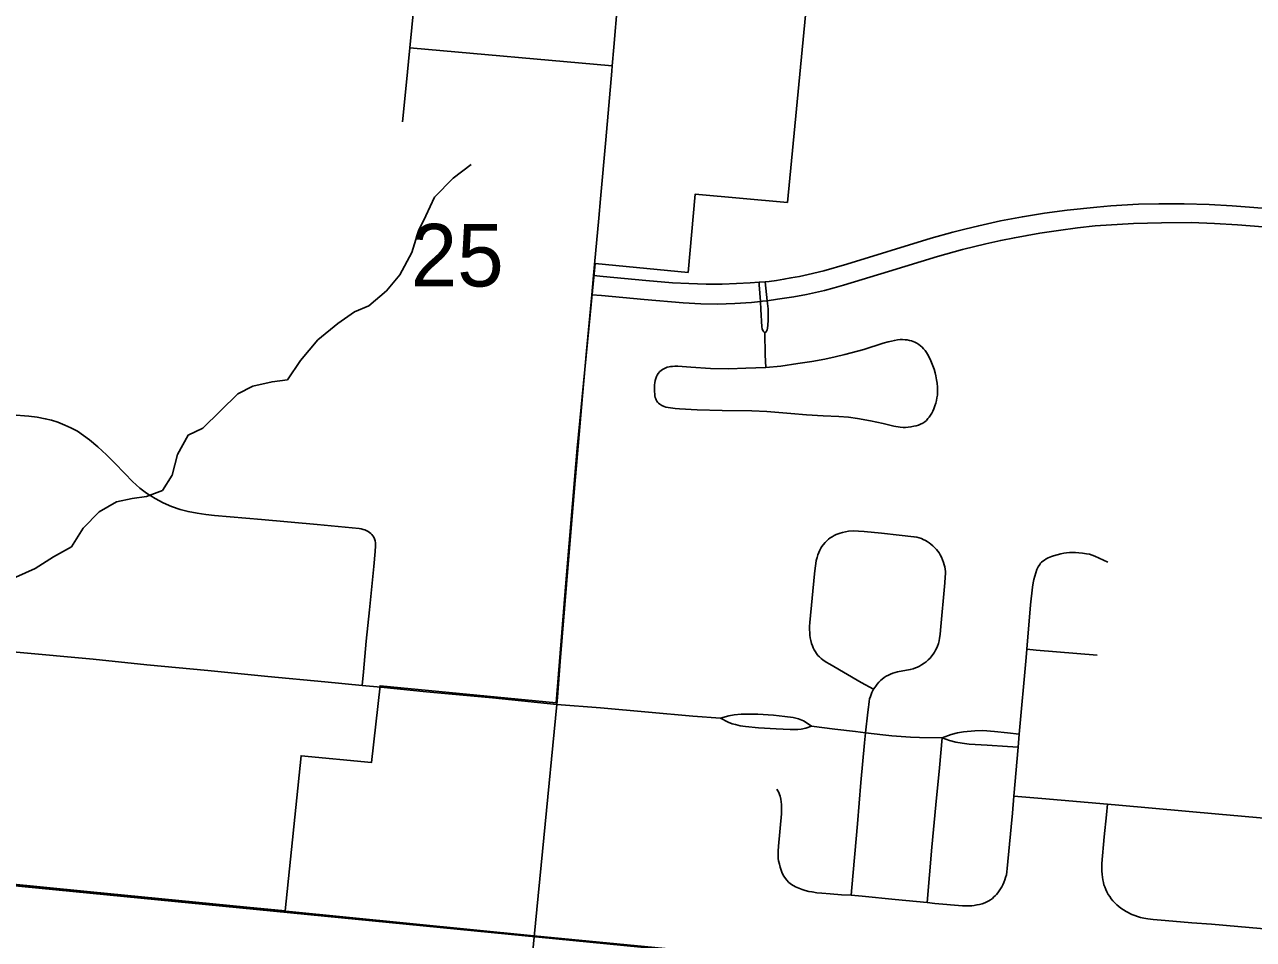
# Model space of a CAD drawing. Extents: x -38.1 to 35.9, y -2.7 to 28.5.
# Drawn here: x 11.157 to 11.979, y 15.188 to 15.8 of the extents above; entities that cross this region are included whole.
import ezdxf

# ---------------------------------------------------------------- set-up
doc = ezdxf.new("R2010")
doc.units = 0
for name, color, linetype in [('GM_X_City_Street', 7, 'Continuous'), ('GM_X_City_Street_Text', 7, 'Continuous'), ('GM_X_Interchange_Ramps', 7, 'Continuous'), ('GM_X_Major_River_Text', 7, 'Continuous'), ('GM_X_Minor_River', 7, 'Continuous'), ('GM_X_Section', 7, 'Continuous'), ('GM_X_US_Route', 7, 'Continuous')]:
    doc.layers.add(name, color=color, linetype=linetype)

msp = doc.modelspace()

# ---------------------------------------------------------------- linework, layer by layer
at = {"layer": 'GM_X_City_Street'}
for points in [[(11.65249, 15.59353), (11.65169, 15.59415), (11.65106, 15.59493), (11.65056, 15.59605), (11.65039, 15.59747), (11.64984, 15.60906), (11.64948, 15.61444), (11.64874, 15.62564), (11.64863, 15.62731)], [(11.65249, 15.59353), (11.65312, 15.59402), (11.65361, 15.59464), (11.65394, 15.59538), (11.65423, 15.59653), (11.65444, 15.59863), (11.65466, 15.60188), (11.65458, 15.60953), (11.65399, 15.61489), (11.65271, 15.62758)], [(11.65318, 15.57039), (11.63966, 15.56974), (11.62844, 15.56947), (11.61599, 15.56972), (11.60294, 15.57051), (11.5943, 15.57112), (11.59234, 15.57113), (11.59066, 15.57105), (11.58938, 15.57093), (11.58835, 15.57072), (11.5872, 15.57043), (11.58611, 15.57003), (11.58498, 15.56944), (11.58406, 15.56896), (11.58313, 15.56829), (11.58229, 15.56753), (11.58119, 15.56626), (11.5805, 15.56517), (11.58002, 15.56427), (11.57951, 15.56295), (11.57915, 15.56151), (11.5789, 15.56012), (11.57871, 15.5586), (11.57858, 15.55559), (11.57865, 15.55403), (11.57876, 15.55258), (11.57894, 15.55128), (11.57917, 15.55025), (11.57943, 15.5493), (11.57974, 15.54861), (11.58013, 15.54782), (11.58059, 15.54718), (11.58132, 15.54643), (11.58215, 15.54571), (11.58356, 15.54489), (11.58517, 15.54422), (11.58629, 15.54384), (11.58777, 15.54355), (11.58927, 15.54331), (11.59238, 15.54289), (11.5954, 15.54262), (11.60714, 15.54197), (11.62388, 15.54162), (11.64377, 15.54128), (11.65372, 15.54083), (11.66983, 15.53949), (11.68033, 15.53863), (11.69147, 15.53804), (11.70204, 15.53758), (11.70839, 15.53698), (11.71445, 15.53615), (11.72305, 15.53459), (11.72733, 15.53366), (11.73157, 15.53272), (11.73879, 15.53103), (11.743, 15.53041), (11.7449, 15.53023), (11.74661, 15.53026), (11.74827, 15.53036), (11.75021, 15.53056), (11.75206, 15.53094), (11.75371, 15.53133), (11.75514, 15.53176), (11.75652, 15.53233), (11.75806, 15.53307), (11.75953, 15.53401), (11.76053, 15.53488), (11.76153, 15.5361), (11.76241, 15.53714), (11.76329, 15.53849), (11.7641, 15.53977), (11.76479, 15.54113), (11.7655, 15.54269), (11.76622, 15.54456), (11.76673, 15.54635), (11.76723, 15.54817), (11.76759, 15.54996), (11.76783, 15.55173), (11.76792, 15.55449), (11.76783, 15.55719), (11.76763, 15.55974), (11.76734, 15.56204), (11.76685, 15.56463), (11.76632, 15.5668), (11.76566, 15.56911), (11.76486, 15.57145), (11.76397, 15.57364), (11.76297, 15.57595), (11.76128, 15.57917), (11.76049, 15.5804), (11.75961, 15.58166), (11.75865, 15.58278), (11.75765, 15.58387), (11.75655, 15.58484), (11.75536, 15.58573), (11.75408, 15.58652), (11.7528, 15.5872), (11.7517, 15.58768), (11.75061, 15.58805), (11.74919, 15.58846), (11.74765, 15.58874), (11.74628, 15.58887), (11.74455, 15.58895), (11.74307, 15.58891), (11.74116, 15.58875), (11.73913, 15.58842), (11.73727, 15.588), (11.73485, 15.58739), (11.7317, 15.58646), (11.71861, 15.58244), (11.706, 15.57902), (11.6994, 15.57732), (11.69265, 15.57587), (11.68386, 15.57436), (11.67457, 15.57288), (11.66305, 15.57129), (11.65318, 15.57039), (11.65277, 15.57886), (11.65249, 15.59353)], [(11.7198, 15.32596), (11.72129, 15.33965), (11.72168, 15.34316), (11.72193, 15.34495), (11.72221, 15.34693), (11.72255, 15.34861), (11.72302, 15.35013), (11.72354, 15.35165), (11.72403, 15.35293), (11.72464, 15.35416), (11.72518, 15.35514), (11.72591, 15.35621), (11.72662, 15.35716), (11.72764, 15.35847), (11.72871, 15.35971), (11.72985, 15.36082), (11.73093, 15.36176), (11.73235, 15.36286), (11.7336, 15.36373), (11.73512, 15.36454), (11.73652, 15.36521), (11.73807, 15.36583), (11.73952, 15.36628), (11.74117, 15.36671), (11.74972, 15.36824), (11.75157, 15.36875), (11.75315, 15.36931), (11.75452, 15.36986), (11.75587, 15.37055), (11.75732, 15.37134), (11.75893, 15.37244), (11.76032, 15.37343), (11.76172, 15.37471), (11.76299, 15.37594), (11.76417, 15.37733), (11.76509, 15.37853), (11.76591, 15.37977), (11.76669, 15.38112), (11.76734, 15.38239), (11.76803, 15.38383), (11.76857, 15.38574), (11.76899, 15.38741), (11.76934, 15.38926), (11.76965, 15.39164), (11.76998, 15.3946), (11.77288, 15.42627), (11.77315, 15.43007), (11.77323, 15.43239), (11.77318, 15.43381), (11.77301, 15.43537), (11.77277, 15.43685), (11.77242, 15.43828), (11.77191, 15.43994), (11.77126, 15.4417), (11.77051, 15.44338), (11.7697, 15.44496), (11.76895, 15.44622), (11.76811, 15.44749), (11.76719, 15.44865), (11.76619, 15.44975), (11.76492, 15.45099), (11.76353, 15.45218), (11.76238, 15.453), (11.76109, 15.4539), (11.75982, 15.45465), (11.75845, 15.45527), (11.75719, 15.4558), (11.75565, 15.45628), (11.75403, 15.45671), (11.75212, 15.45705), (11.74238, 15.45822), (11.73038, 15.45937), (11.71886, 15.46052), (11.71503, 15.46086), (11.71149, 15.46096), (11.70851, 15.46078), (11.7064, 15.46044), (11.70436, 15.45998), (11.7029, 15.45958), (11.7015, 15.45911), (11.70007, 15.45852), (11.69878, 15.45789), (11.69752, 15.45712), (11.69625, 15.45633), (11.69497, 15.45539), (11.69386, 15.45436), (11.69279, 15.45325), (11.69155, 15.45177), (11.69061, 15.4505), (11.68987, 15.44933), (11.68913, 15.44799), (11.68859, 15.44665), (11.68798, 15.44503), (11.68741, 15.44322), (11.68687, 15.44113), (11.68649, 15.43909), (11.68605, 15.43611), (11.68566, 15.43217), (11.68258, 15.39963), (11.68239, 15.39699), (11.68234, 15.39476), (11.68243, 15.39304), (11.68261, 15.39115), (11.68284, 15.38938), (11.68325, 15.38759), (11.68375, 15.38572), (11.68428, 15.38414), (11.68485, 15.38276), (11.68551, 15.38143), (11.68625, 15.38009), (11.6871, 15.37891), (11.68798, 15.37771), (11.68902, 15.37667), (11.69012, 15.37566), (11.69126, 15.37476), (11.69345, 15.37323), (11.69587, 15.37183), (11.71687, 15.35967), (11.72518, 15.35514)], [(11.66039, 15.2883), (11.66171, 15.286), (11.66229, 15.28472), (11.66272, 15.28357), (11.66319, 15.28164), (11.66344, 15.27978), (11.66362, 15.27806), (11.66368, 15.27658), (11.66362, 15.27422), (11.66349, 15.27177), (11.66156, 15.25016), (11.66128, 15.24679), (11.66125, 15.24381), (11.66142, 15.24193), (11.66169, 15.24021), (11.66216, 15.23805), (11.66263, 15.23606), (11.66327, 15.23412), (11.66382, 15.23265), (11.66452, 15.23121), (11.66514, 15.22999), (11.66685, 15.22758), (11.66846, 15.22587), (11.67031, 15.22445), (11.67291, 15.22299), (11.67516, 15.222), (11.67742, 15.22115), (11.6795, 15.22047), (11.68181, 15.21988), (11.68403, 15.21946), (11.68727, 15.219), (11.6906, 15.21867), (11.69619, 15.21821), (11.70378, 15.21765), (11.71009, 15.21722), (11.71751, 15.21655), (11.73952, 15.21452), (11.76095, 15.21237), (11.76612, 15.21186), (11.78465, 15.21025), (11.78892, 15.21017), (11.79081, 15.21025), (11.79254, 15.21045), (11.79435, 15.21078), (11.79607, 15.21116), (11.79788, 15.21164), (11.79951, 15.21227), (11.80088, 15.21283), (11.80219, 15.21355), (11.80339, 15.21427), (11.80464, 15.21521), (11.80571, 15.21613), (11.80656, 15.21686), (11.80742, 15.21785), (11.80828, 15.21896), (11.80914, 15.22019), (11.81008, 15.22164), (11.81087, 15.2229), (11.81161, 15.2242), (11.81231, 15.22578), (11.81301, 15.22751), (11.8135, 15.22915), (11.81398, 15.23099), (11.81432, 15.23289), (11.81463, 15.23519), (11.81721, 15.26301), (11.81811, 15.27228), (11.81907, 15.28356), (11.82187, 15.31634), (11.82261, 15.32501), (11.82718, 15.37629), (11.82769, 15.38193), (11.83025, 15.41148), (11.83146, 15.42336), (11.83191, 15.42635), (11.83241, 15.42857), (11.83303, 15.43079), (11.83368, 15.43297), (11.83442, 15.43506), (11.83537, 15.43704), (11.83629, 15.43848), (11.83689, 15.43934), (11.83759, 15.44005), (11.83849, 15.44082), (11.83948, 15.44152), (11.84067, 15.44222), (11.84202, 15.44292), (11.84305, 15.44341), (11.84416, 15.44386), (11.84544, 15.44435), (11.8479, 15.44506), (11.8505, 15.44562), (11.85243, 15.446), (11.85427, 15.44628), (11.85625, 15.44645), (11.85809, 15.44654), (11.86032, 15.44649), (11.86253, 15.44638), (11.86492, 15.44613), (11.86755, 15.44575), (11.86956, 15.44534), (11.87137, 15.44481), (11.87322, 15.44411), (11.88197, 15.44004)], [(11.82769, 15.38193), (11.83401, 15.3813), (11.87471, 15.37776)], [(11.5133, 15.34492), (11.5426, 15.34262), (11.57467, 15.33974), (11.60434, 15.33717), (11.6228, 15.33579)], [(11.6228, 15.33579), (11.62831, 15.33736), (11.63201, 15.33802), (11.63661, 15.33835), (11.64097, 15.33851), (11.6477, 15.33834), (11.6583, 15.33774), (11.66571, 15.33695), (11.67138, 15.33612), (11.675, 15.33522), (11.67821, 15.33399), (11.68083, 15.33227), (11.68355, 15.33029)], [(11.6228, 15.33579), (11.62798, 15.333), (11.63053, 15.33202), (11.63277, 15.33138), (11.63603, 15.3307), (11.63955, 15.33023), (11.64825, 15.32928), (11.66011, 15.32856), (11.66933, 15.32807), (11.67442, 15.32815), (11.67673, 15.3284), (11.67985, 15.32914), (11.68355, 15.33029)], [(11.68355, 15.33029), (11.69934, 15.32846), (11.71298, 15.32682), (11.7198, 15.32596), (11.73131, 15.32451), (11.73732, 15.32385), (11.74357, 15.32344), (11.74982, 15.32304), (11.75586, 15.3228), (11.7711, 15.32254)], [(11.71009, 15.21722), (11.71056, 15.22243), (11.71443, 15.265), (11.71662, 15.29279), (11.71916, 15.3193), (11.7198, 15.32596)], [(11.76095, 15.21237), (11.76409, 15.2494), (11.76676, 15.27781), (11.76923, 15.30259), (11.7711, 15.32254)], [(11.7711, 15.32254), (11.77702, 15.32484), (11.78122, 15.32591), (11.7854, 15.32665), (11.79281, 15.32736), (11.79833, 15.32742), (11.80604, 15.3269), (11.81484, 15.32592), (11.82261, 15.32501)], [(11.7711, 15.32254), (11.77603, 15.32081), (11.78015, 15.31974), (11.78442, 15.31901), (11.78919, 15.31843), (11.80127, 15.31769), (11.8147, 15.31682), (11.82187, 15.31634)], [(11.81907, 15.28356), (11.83782, 15.28203), (11.88167, 15.27814), (11.8892, 15.27747), (11.95604, 15.27153), (11.98884, 15.26854), (12.02289, 15.2657)], [(11.88167, 15.27814), (11.88098, 15.27116), (11.87951, 15.25633), (11.87796, 15.2384), (11.8779, 15.23596), (11.8779, 15.2335), (11.87802, 15.23115), (11.8782, 15.22926), (11.87851, 15.2275), (11.87887, 15.22571), (11.87929, 15.2242), (11.87976, 15.22285), (11.88049, 15.22104), (11.88124, 15.21956), (11.88217, 15.21788), (11.88312, 15.21645), (11.88418, 15.21492), (11.88531, 15.21357), (11.88653, 15.2122), (11.88783, 15.21097), (11.8892, 15.20978), (11.89063, 15.20869), (11.89236, 15.20748), (11.89421, 15.20641), (11.89802, 15.20449), (11.89997, 15.20365), (11.90173, 15.20304), (11.90374, 15.20246), (11.90601, 15.20193), (11.90864, 15.20152), (11.91217, 15.20114), (11.92018, 15.20034), (11.93814, 15.19889), (11.95118, 15.19792), (11.99394, 15.19424)]]:
    msp.add_lwpolyline(points, dxfattribs=at)
at = {"layer": 'GM_X_City_Street_Text'}
for points in [[(11.53789, 15.6318), (11.54439, 15.63118), (11.57291, 15.62847), (11.59067, 15.62699), (11.6016, 15.62641), (11.61327, 15.626), (11.624, 15.6261), (11.63359, 15.62639), (11.64262, 15.62691), (11.64863, 15.62731), (11.65271, 15.62758), (11.65536, 15.62789), (11.66029, 15.62853), (11.66523, 15.62937), (11.66989, 15.63021), (11.67566, 15.63126), (11.68151, 15.63253), (11.6918, 15.63503), (11.70737, 15.63943), (11.76381, 15.65669), (11.77812, 15.66076), (11.78631, 15.66291), (11.79557, 15.66512), (11.8101, 15.66835), (11.82472, 15.67118), (11.8394, 15.67358), (11.85477, 15.67558), (11.87454, 15.67752), (11.88378, 15.67832), (11.90238, 15.67946), (11.91605, 15.67982), (11.93283, 15.6798), (11.9496, 15.67934), (11.96511, 15.67852), (11.9967, 15.67592)], [(11.64948, 15.61444), (11.65083, 15.61457), (11.65399, 15.61489), (11.66095, 15.61589), (11.6718, 15.61751), (11.68031, 15.61911), (11.68627, 15.62041), (11.69244, 15.62189), (11.69877, 15.62353), (11.70517, 15.62534), (11.73526, 15.63455), (11.76787, 15.6445), (11.78464, 15.64916), (11.80033, 15.6531), (11.81023, 15.65535), (11.81944, 15.65707), (11.82791, 15.65863), (11.83636, 15.66004), (11.84887, 15.66192), (11.86161, 15.66365), (11.87336, 15.66505), (11.89909, 15.66656), (11.91772, 15.66715), (11.9376, 15.66717), (11.95313, 15.66672), (11.96863, 15.66583), (11.99401, 15.66372)], [(11.53671, 15.61895), (11.54316, 15.61836), (11.57183, 15.61573), (11.59779, 15.6135), (11.60954, 15.61286), (11.62068, 15.61271), (11.63243, 15.61308), (11.64354, 15.61383), (11.64948, 15.61444)]]:
    msp.add_lwpolyline(points, dxfattribs=at)
at = {"layer": 'GM_X_Interchange_Ramps'}
for p, q in [((11.5137, 15.34987), (11.51561, 15.37365)), ((11.5133, 15.34492), (11.5137, 15.34987))]:
    msp.add_line(p, q, dxfattribs=at)
for points in [[(11.53789, 15.6318), (11.53858, 15.63929), (11.54132, 15.67019), (11.54257, 15.68309), (11.54617, 15.72268), (11.55005, 15.76849), (11.55027, 15.772), (11.55133, 15.78458), (11.55396, 15.81365), (11.55573, 15.83533), (11.55665, 15.84891), (11.55765, 15.86062), (11.56002, 15.88846), (11.56062, 15.89764), (11.56179, 15.91306), (11.56392, 15.93779), (11.56473, 15.94711), (11.56559, 15.95762), (11.56583, 15.96053)], [(11.52558, 15.49473), (11.52642, 15.50481), (11.53058, 15.55135), (11.53326, 15.58136), (11.53671, 15.61895), (11.53789, 15.6318)], [(11.51561, 15.37365), (11.51975, 15.42518), (11.52558, 15.49473)], [(11.49811, 15.18954), (11.50455, 15.25558), (11.5133, 15.34492)], [(11.47425, 14.93452), (11.48082, 15.00035), (11.48771, 15.07998), (11.49811, 15.18954)]]:
    msp.add_lwpolyline(points, dxfattribs=at)
at = {"layer": 'GM_X_Major_River_Text'}
for p, q in [((11.41488, 15.78403), (11.55027, 15.772)), ((11.38319, 15.35756), (11.3955, 15.35638))]:
    msp.add_line(p, q, dxfattribs=at)
for points in [[(11.41488, 15.78403), (11.41626, 15.79781), (11.41797, 15.8137), (11.41921, 15.82557), (11.42048, 15.83749), (11.42794, 15.90443), (11.42965, 15.92109), (11.43256, 15.94766), (11.43355, 15.95685), (11.43493, 15.96988), (11.44088, 16.02529)], [(11.41014, 15.73472), (11.41248, 15.75897), (11.41488, 15.78403)], [(11.14879, 15.53872), (11.16011, 15.53773), (11.16578, 15.53699), (11.17108, 15.53604), (11.17536, 15.53496), (11.17951, 15.53361), (11.18427, 15.53181), (11.18823, 15.52993), (11.19258, 15.52762), (11.19669, 15.5249), (11.20071, 15.52194), (11.20639, 15.51726), (11.21214, 15.51184), (11.21746, 15.50663), (11.22426, 15.49935), (11.22942, 15.49407), (11.23447, 15.48959), (11.23887, 15.48626), (11.24453, 15.48261), (11.24992, 15.47971), (11.25555, 15.47729), (11.26137, 15.47532), (11.26669, 15.4739), (11.27274, 15.47286), (11.27848, 15.47205), (11.2844, 15.4714), (11.31572, 15.46859), (11.35296, 15.46531), (11.38105, 15.46263), (11.38236, 15.46239), (11.38372, 15.46202), (11.38489, 15.46165), (11.38586, 15.46119), (11.38701, 15.46062), (11.38803, 15.45996), (11.38886, 15.45927), (11.38964, 15.45848), (11.39029, 15.4577), (11.39091, 15.4568), (11.39144, 15.45577), (11.3919, 15.45441), (11.39202, 15.45298), (11.39194, 15.45092), (11.39171, 15.44726), (11.39081, 15.43723), (11.38797, 15.40819), (11.38588, 15.38726), (11.38407, 15.36662), (11.38319, 15.35756)], [(11.0843, 15.38649), (11.09569, 15.38536), (11.15192, 15.37986), (11.20324, 15.37508), (11.23903, 15.37146), (11.27983, 15.36766), (11.31996, 15.3637), (11.35815, 15.35995), (11.38319, 15.35756)], [(11.3955, 15.35638), (11.42622, 15.35342), (11.47035, 15.34929), (11.5133, 15.34492)]]:
    msp.add_lwpolyline(points, dxfattribs=at)
at = {"layer": 'GM_X_Section'}
msp.add_lwpolyline([(11.15138, 15.42997), (11.16434, 15.43589), (11.17656, 15.44371), (11.18878, 15.4504), (11.19651, 15.46283), (11.20726, 15.4737), (11.21871, 15.4804), (11.22936, 15.48255), (11.23885, 15.48395), (11.24952, 15.488), (11.25609, 15.49816), (11.25966, 15.51216), (11.26664, 15.52498), (11.27656, 15.52979), (11.29996, 15.55266), (11.30988, 15.55786), (11.32281, 15.56074), (11.33306, 15.56213), (11.34194, 15.57493), (11.35348, 15.58883), (11.36688, 15.59967), (11.37797, 15.60751), (11.38749, 15.61157), (11.39937, 15.62167), (11.40822, 15.6322), (11.41636, 15.64727), (11.4207, 15.66164), (11.42575, 15.67183), (11.43158, 15.68428), (11.44387, 15.69703), (11.45611, 15.70599)], dxfattribs=at)
at = {"layer": 'GM_X_US_Route'}
msp.add_lwpolyline([(11.07884, 16.22782), (11.4865, 16.19596), (12.08589, 16.14841), (11.99273, 15.14118), (10.98915, 15.23941)], close=True, dxfattribs=at)
for points in [[(11.69275, 15.94299), (11.66754, 15.68074), (11.60583, 15.6862), (11.60112, 15.6339), (11.53889, 15.63981), (11.52698, 15.51629), (11.52604, 15.50583), (11.51937, 15.42621), (11.51292, 15.34594), (11.39512, 15.35741), (11.3894, 15.3061), (11.34227, 15.31064), (11.33168, 15.20679), (11.30597, 15.20932), (11.20146, 15.21962), (11.19909, 15.21985), (11.00115, 15.23935)], [(14.91464, 14.86936), (13.51079, 14.99906), (13.50584, 14.99953), (12.87542, 15.05878), (12.53822, 15.08969), (12.05867, 15.13731), (11.99495, 15.14243), (11.73374, 15.16733), (11.49788, 15.19007), (11.33193, 15.20653), (10.99454, 15.23933), (10.66361, 15.26985), (10.52889, 15.2826), (10.37102, 15.29767)], [(10.37102, 15.29767), (10.52889, 15.2826), (10.66361, 15.26985), (10.99454, 15.23933), (11.33193, 15.20653), (11.49788, 15.19007), (11.73374, 15.16733), (11.99495, 15.14243), (12.05867, 15.13731), (12.53822, 15.08969), (12.87542, 15.05878), (13.50584, 14.99953), (13.51079, 14.99906), (14.91464, 14.86936)], [(10.37102, 15.29767), (10.52889, 15.2826), (10.66361, 15.26985), (10.99454, 15.23933), (11.33193, 15.20653), (11.49788, 15.19007), (11.73374, 15.16733), (11.99495, 15.14243), (12.05867, 15.13731), (12.53822, 15.08969), (12.87542, 15.05878), (13.50584, 14.99953), (13.51079, 14.99906), (14.91464, 14.86936)], [(14.91464, 14.86936), (13.51079, 14.99906), (13.50584, 14.99953), (12.87542, 15.05878), (12.53822, 15.08969), (12.05867, 15.13731), (11.99495, 15.14243), (11.73374, 15.16733), (11.49788, 15.19007), (11.33193, 15.20653), (10.99454, 15.23933), (10.66361, 15.26985), (10.52889, 15.2826), (10.37102, 15.29767)]]:
    msp.add_lwpolyline(points, dxfattribs=at)

# ---------------------------------------------------------------- texts
at = {"layer": 'GM_X_Minor_River'}
msp.add_text('25', height=0.041856, rotation=0.00001, dxfattribs=at).set_placement((11.41553, 15.62449))

doc.saveas('drawing.dxf')
